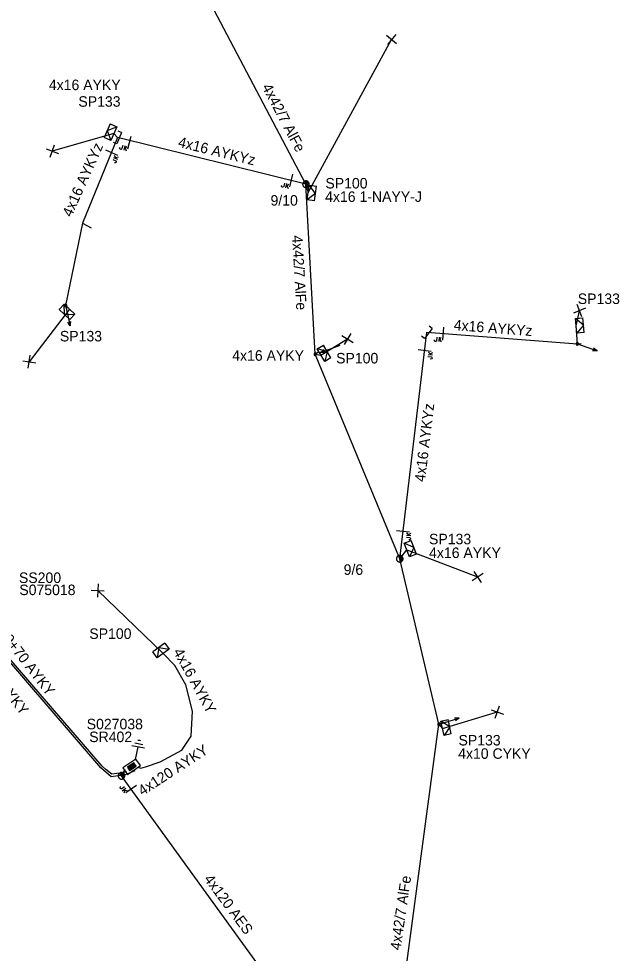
# Model space of a CAD drawing. Extents: x -788458 to -786145, y -1154772 to -1152372.
# Drawn here: x -786436.8 to -786379.6, y -1153446 to -1153357 of the extents above; entities that cross this region are included whole.
import ezdxf

# ---------------------------------------------------------------- set-up
doc = ezdxf.new("R2010")
doc.units = 0
for name, color, linetype in [('Vrstva 1', 7, 'Continuous'), ('Vrstva 12', 7, 'Continuous'), ('Vrstva 13', 7, 'Continuous'), ('Vrstva 14', 7, 'Continuous'), ('Vrstva 15', 7, 'Continuous'), ('Vrstva 18', 7, 'Continuous'), ('Vrstva 2', 7, 'Continuous'), ('Vrstva 28', 7, 'Continuous'), ('Vrstva 29', 7, 'Continuous'), ('Vrstva 30', 7, 'Continuous'), ('Vrstva 31', 7, 'Continuous'), ('Vrstva 33', 7, 'Continuous'), ('Vrstva 34', 7, 'Continuous'), ('Vrstva 5', 7, 'Continuous'), ('Vrstva 50', 7, 'Continuous'), ('Vrstva 51', 7, 'Continuous'), ('Vrstva 52', 7, 'Continuous'), ('Vrstva 53', 7, 'Continuous'), ('Vrstva 54', 7, 'Continuous'), ('Vrstva 55', 7, 'Continuous'), ('Vrstva 59', 7, 'Continuous'), ('Vrstva 6', 7, 'Continuous'), ('Vrstva 8', 7, 'Continuous'), ('Vrstva 9', 7, 'Continuous')]:
    doc.layers.add(name, color=color, linetype=linetype)

# ---------------------------------------------------------------- blocks, each defined once
blk = doc.blocks.new('NN440')
at = {"layer": 'Vrstva 2'}
for points in [[(0.63, 0), (0.63, 0.06), (0.62, 0.13), (0.6, 0.19), (0.58, 0.25), (0.55, 0.31), (0.51, 0.37), (0.47, 0.42), (0.42, 0.46), (0.37, 0.51), (0.32, 0.54), (0.26, 0.57), (0.2, 0.59), (0.13, 0.61), (0.07, 0.62), (0, 0.63), (-0.06, 0.62), (-0.13, 0.61), (-0.19, 0.59), (-0.26, 0.57), (-0.31, 0.54), (-0.37, 0.51), (-0.42, 0.46), (-0.47, 0.42), (-0.51, 0.37), (-0.54, 0.31), (-0.57, 0.25), (-0.6, 0.19), (-0.62, 0.13), (-0.63, 0.06), (-0.63, 0), (-0.63, -0.07), (-0.62, -0.14), (-0.6, -0.2), (-0.57, -0.26), (-0.54, -0.32), (-0.51, -0.37), (-0.47, -0.43), (-0.42, -0.47), (-0.37, -0.51), (-0.31, -0.55), (-0.26, -0.58), (-0.19, -0.6), (-0.13, -0.62), (-0.06, -0.63), (0, -0.63), (0.07, -0.63), (0.13, -0.62), (0.2, -0.6), (0.26, -0.58), (0.32, -0.55), (0.37, -0.51), (0.42, -0.47), (0.47, -0.43), (0.51, -0.37), (0.55, -0.32), (0.58, -0.26), (0.6, -0.2), (0.62, -0.14), (0.63, -0.07), (0.63, 0)], [(-0.63, 0), (0.63, 0)], [(-0.6, -0.18), (0.57, -0.18)], [(-0.51, -0.32), (0.5, -0.32)], [(-0.37, -0.47), (0.35, -0.47)]]:
    blk.add_lwpolyline(points, dxfattribs=at)
blk = doc.blocks.new('NN560')
at = {"layer": 'Vrstva 2'}
for points in [[(1.999, -0.001), (1.59, 0.141)], [(0, -0.001), (1.999, -0.001)], [(1.999, -0.001), (1.59, -0.134)]]:
    blk.add_lwpolyline(points, dxfattribs=at)
blk = doc.blocks.new('NN840')
at = {"layer": 'Vrstva 15'}
for points in [[(0.003, 0.619), (0.003, -0.631)], [(-0.745, -0.71), (-0.745, -0.66)], [(-0.73, -0.764), (-0.745, -0.71)], [(-0.657, -0.798), (-0.73, -0.764)], [(-0.627, -0.798), (-0.657, -0.798)], [(-0.558, -0.764), (-0.627, -0.798)], [(-0.538, -0.71), (-0.558, -0.764)], [(-0.538, -0.385), (-0.538, -0.71)], [(-0.332, -0.385), (-0.332, -0.798)], [(-0.332, -0.641), (-0.125, -0.385)], [(-0.263, -0.557), (-0.091, -0.798)]]:
    blk.add_lwpolyline(points, dxfattribs=at)
blk = doc.blocks.new('NN565')
at = {"layer": 'Vrstva 2'}
for points in [[(0.015, 0.528), (0.015, 2.528)], [(0.157, 0.937), (0.015, 0.528), (-0.119, 0.937)]]:
    blk.add_lwpolyline(points, dxfattribs=at)
blk = doc.blocks.new('NN800')
at = {"layer": 'Vrstva 1'}
for points in [[(-0.442, 0.442), (0.442, -0.442)], [(-0.442, -0.442), (0.442, 0.442)]]:
    blk.add_lwpolyline(points, dxfattribs=at)
blk = doc.blocks.new('NN620')
at = {"layer": 'Vrstva 8'}
for points in [[(0.752, 0.004), (-0.748, 0.004)], [(-0.748, 0.004), (-0.748, -0.746)], [(0.752, -0.746), (0.752, 0.004)], [(-0.748, -0.746), (0.752, -0.746)], [(0.368, -0.18), (-0.376, -0.18)], [(-0.376, -0.18), (-0.376, -0.558)], [(-0.376, -0.558), (0.368, -0.558)], [(0.321, -0.227), (-0.329, -0.227)], [(-0.329, -0.227), (-0.329, -0.51)], [(-0.329, -0.51), (0.321, -0.51)], [(0.274, -0.274), (-0.281, -0.274)], [(-0.281, -0.274), (-0.281, -0.463)], [(-0.281, -0.463), (0.274, -0.463)], [(0.227, -0.321), (-0.234, -0.321)], [(-0.234, -0.321), (-0.234, -0.416)], [(-0.234, -0.416), (0.227, -0.416)], [(-0.193, -0.369), (0.185, -0.369)], [(0.227, -0.416), (0.227, -0.321)], [(0.274, -0.463), (0.274, -0.274)], [(0.321, -0.51), (0.321, -0.227)], [(0.368, -0.558), (0.368, -0.18)]]:
    blk.add_lwpolyline(points, dxfattribs=at)
blk = doc.blocks.new('NN630')
at = {"layer": 'Vrstva 9'}
for points in [[(-0.003, -0.7), (-0.703, 0)], [(-0.703, -0.7), (-0.703, 0), (0.697, 0), (0.697, -0.7)], [(-0.703, -0.7), (0.697, -0.7)], [(-0.003, -0.7), (0.697, 0)]]:
    blk.add_lwpolyline(points, dxfattribs=at)
blk = doc.blocks.new('NN810')
at = {"layer": 'Vrstva 14'}
for points in [[(0.004, -0.64), (0.004, -1.89)], [(0.629, -1.89), (-0.621, -1.89)], [(0.388, -2.2), (-0.399, -2.2)], [(0.004, -2.515), (-0.124, -2.515)], [(0.137, -2.515), (0.004, -2.515)]]:
    blk.add_lwpolyline(points, dxfattribs=at)
blk = doc.blocks.new('NN500')
at = {"layer": 'Vrstva 2'}
for points in [[(0, -0.24), (0.02, -0.23), (0.05, -0.23), (0.07, -0.22), (0.09, -0.22), (0.12, -0.2), (0.14, -0.19), (0.16, -0.18), (0.17, -0.16), (0.19, -0.14), (0.2, -0.12), (0.21, -0.1), (0.22, -0.07), (0.23, -0.05), (0.23, -0.02), (0.23, 0), (0.23, 0.02), (0.23, 0.05), (0.22, 0.07), (0.21, 0.1), (0.2, 0.12), (0.19, 0.14), (0.17, 0.16), (0.16, 0.17), (0.14, 0.19), (0.12, 0.2), (0.09, 0.21), (0.07, 0.22), (0.05, 0.23), (0.02, 0.23), (0, 0.23), (-0.03, 0.23), (-0.05, 0.23), (-0.07, 0.22), (-0.1, 0.21), (-0.12, 0.2), (-0.14, 0.19), (-0.16, 0.17), (-0.18, 0.16), (-0.19, 0.14), (-0.2, 0.12), (-0.22, 0.1), (-0.22, 0.07), (-0.23, 0.05), (-0.23, 0.02), (-0.24, 0), (-0.23, -0.02), (-0.23, -0.05), (-0.22, -0.07), (-0.22, -0.1), (-0.2, -0.12), (-0.19, -0.14), (-0.18, -0.16), (-0.16, -0.18), (-0.14, -0.19), (-0.12, -0.2), (-0.1, -0.22), (-0.07, -0.22), (-0.05, -0.23), (-0.03, -0.23), (0, -0.24)], [(0, -0.24), (0.02, -0.23), (0.05, -0.23), (0.07, -0.22), (0.09, -0.22), (0.12, -0.2), (0.14, -0.19), (0.16, -0.18), (0.17, -0.16), (0.19, -0.14), (0.2, -0.12), (0.21, -0.1), (0.22, -0.07), (0.23, -0.05), (0.23, -0.02), (0.23, 0), (0.23, 0.02), (0.23, 0.05), (0.22, 0.07), (0.21, 0.1), (0.2, 0.12), (0.19, 0.14), (0.17, 0.16), (0.16, 0.17), (0.14, 0.19), (0.12, 0.2), (0.09, 0.21), (0.07, 0.22), (0.05, 0.23), (0.02, 0.23), (0, 0.23), (-0.03, 0.23), (-0.05, 0.23), (-0.07, 0.22), (-0.1, 0.21), (-0.12, 0.2), (-0.14, 0.19), (-0.16, 0.17), (-0.18, 0.16), (-0.19, 0.14), (-0.2, 0.12), (-0.22, 0.1), (-0.22, 0.07), (-0.23, 0.05), (-0.23, 0.02), (-0.24, 0), (-0.23, -0.02), (-0.23, -0.05), (-0.22, -0.07), (-0.22, -0.1), (-0.2, -0.12), (-0.19, -0.14), (-0.18, -0.16), (-0.16, -0.18), (-0.14, -0.19), (-0.12, -0.2), (-0.1, -0.22), (-0.07, -0.22), (-0.05, -0.23), (-0.03, -0.23), (0, -0.24)], [(0, -0.21), (0.02, -0.2), (0.04, -0.2), (0.06, -0.2), (0.08, -0.19), (0.1, -0.18), (0.12, -0.17), (0.14, -0.15), (0.15, -0.14), (0.16, -0.12), (0.18, -0.1), (0.19, -0.08), (0.19, -0.06), (0.2, -0.04), (0.2, -0.02), (0.2, 0), (0.2, 0.02), (0.2, 0.04), (0.19, 0.06), (0.19, 0.08), (0.18, 0.1), (0.16, 0.12), (0.15, 0.14), (0.14, 0.15), (0.12, 0.17), (0.1, 0.18), (0.08, 0.19), (0.06, 0.19), (0.04, 0.2), (0.02, 0.2), (0, 0.2), (-0.02, 0.2), (-0.04, 0.2), (-0.06, 0.19), (-0.08, 0.19), (-0.1, 0.18), (-0.12, 0.17), (-0.14, 0.15), (-0.15, 0.14), (-0.17, 0.12), (-0.18, 0.1), (-0.19, 0.08), (-0.2, 0.06), (-0.2, 0.04), (-0.21, 0.02), (-0.21, 0), (-0.21, -0.02), (-0.2, -0.04), (-0.2, -0.06), (-0.19, -0.08), (-0.18, -0.1), (-0.17, -0.12), (-0.15, -0.14), (-0.14, -0.15), (-0.12, -0.17), (-0.1, -0.18), (-0.08, -0.19), (-0.06, -0.2), (-0.04, -0.2), (-0.02, -0.2), (0, -0.21)], [(0, -0.18), (0.02, -0.18), (0.04, -0.17), (0.05, -0.17), (0.07, -0.16), (0.09, -0.15), (0.1, -0.14), (0.12, -0.13), (0.13, -0.12), (0.14, -0.1), (0.15, -0.09), (0.16, -0.07), (0.17, -0.05), (0.17, -0.04), (0.17, -0.02), (0.17, 0), (0.17, 0.02), (0.17, 0.04), (0.17, 0.05), (0.16, 0.07), (0.15, 0.09), (0.14, 0.1), (0.13, 0.12), (0.12, 0.13), (0.1, 0.14), (0.09, 0.15), (0.07, 0.16), (0.05, 0.17), (0.04, 0.17), (0.02, 0.17), (0, 0.18), (-0.02, 0.17), (-0.04, 0.17), (-0.06, 0.17), (-0.07, 0.16), (-0.09, 0.15), (-0.1, 0.14), (-0.12, 0.13), (-0.13, 0.12), (-0.14, 0.1), (-0.15, 0.09), (-0.16, 0.07), (-0.17, 0.05), (-0.17, 0.04), (-0.18, 0.02), (-0.18, 0), (-0.18, -0.02), (-0.17, -0.04), (-0.17, -0.05), (-0.16, -0.07), (-0.15, -0.09), (-0.14, -0.1), (-0.13, -0.12), (-0.12, -0.13), (-0.1, -0.14), (-0.09, -0.15), (-0.07, -0.16), (-0.06, -0.17), (-0.04, -0.17), (-0.02, -0.18), (0, -0.18)], [(0, -0.15), (0.01, -0.15), (0.03, -0.14), (0.04, -0.14), (0.06, -0.13), (0.07, -0.13), (0.08, -0.12), (0.1, -0.11), (0.11, -0.1), (0.12, -0.09), (0.13, -0.07), (0.13, -0.06), (0.14, -0.05), (0.14, -0.03), (0.14, -0.02), (0.14, 0), (0.14, 0.01), (0.14, 0.03), (0.14, 0.04), (0.13, 0.06), (0.13, 0.07), (0.12, 0.09), (0.11, 0.1), (0.1, 0.11), (0.08, 0.12), (0.07, 0.13), (0.06, 0.13), (0.04, 0.14), (0.03, 0.14), (0.01, 0.14), (0, 0.15), (-0.02, 0.14), (-0.03, 0.14), (-0.05, 0.14), (-0.06, 0.13), (-0.07, 0.13), (-0.09, 0.12), (-0.1, 0.11), (-0.11, 0.1), (-0.12, 0.09), (-0.13, 0.07), (-0.13, 0.06), (-0.14, 0.04), (-0.14, 0.03), (-0.15, 0.01), (-0.15, 0), (-0.15, -0.02), (-0.14, -0.03), (-0.14, -0.05), (-0.13, -0.06), (-0.13, -0.07), (-0.12, -0.09), (-0.11, -0.1), (-0.1, -0.11), (-0.09, -0.12), (-0.07, -0.13), (-0.06, -0.13), (-0.05, -0.14), (-0.03, -0.14), (-0.02, -0.15), (0, -0.15)], [(0, -0.12), (0.01, -0.12), (0.02, -0.11), (0.03, -0.11), (0.05, -0.11), (0.06, -0.1), (0.07, -0.09), (0.08, -0.09), (0.09, -0.08), (0.09, -0.07), (0.1, -0.06), (0.11, -0.05), (0.11, -0.04), (0.11, -0.02), (0.11, -0.01), (0.12, 0), (0.11, 0.01), (0.11, 0.02), (0.11, 0.04), (0.11, 0.05), (0.1, 0.06), (0.09, 0.07), (0.09, 0.08), (0.08, 0.09), (0.07, 0.09), (0.06, 0.1), (0.05, 0.11), (0.03, 0.11), (0.02, 0.11), (0.01, 0.12), (0, 0.12), (-0.01, 0.12), (-0.03, 0.11), (-0.04, 0.11), (-0.05, 0.11), (-0.06, 0.1), (-0.07, 0.09), (-0.08, 0.09), (-0.09, 0.08), (-0.1, 0.07), (-0.1, 0.06), (-0.11, 0.05), (-0.11, 0.04), (-0.12, 0.02), (-0.12, 0.01), (-0.12, 0), (-0.12, -0.01), (-0.12, -0.02), (-0.11, -0.04), (-0.11, -0.05), (-0.1, -0.06), (-0.1, -0.07), (-0.09, -0.08), (-0.08, -0.09), (-0.07, -0.09), (-0.06, -0.1), (-0.05, -0.11), (-0.04, -0.11), (-0.03, -0.11), (-0.01, -0.12), (0, -0.12)], [(0, -0.09), (0.01, -0.09), (0.02, -0.09), (0.03, -0.08), (0.03, -0.08), (0.04, -0.08), (0.05, -0.07), (0.06, -0.07), (0.06, -0.06), (0.07, -0.05), (0.07, -0.04), (0.08, -0.04), (0.08, -0.03), (0.08, -0.02), (0.09, -0.01), (0.09, 0), (0.09, 0.01), (0.08, 0.02), (0.08, 0.03), (0.08, 0.03), (0.07, 0.04), (0.07, 0.05), (0.06, 0.06), (0.06, 0.06), (0.05, 0.07), (0.04, 0.07), (0.03, 0.08), (0.03, 0.08), (0.02, 0.08), (0.01, 0.09), (0, 0.09), (-0.01, 0.09), (-0.02, 0.08), (-0.03, 0.08), (-0.04, 0.08), (-0.04, 0.07), (-0.05, 0.07), (-0.06, 0.06), (-0.07, 0.06), (-0.07, 0.05), (-0.08, 0.04), (-0.08, 0.03), (-0.08, 0.03), (-0.09, 0.02), (-0.09, 0.01), (-0.09, 0), (-0.09, -0.01), (-0.09, -0.02), (-0.08, -0.03), (-0.08, -0.04), (-0.08, -0.04), (-0.07, -0.05), (-0.07, -0.06), (-0.06, -0.07), (-0.05, -0.07), (-0.04, -0.08), (-0.04, -0.08), (-0.03, -0.08), (-0.02, -0.09), (-0.01, -0.09), (0, -0.09)], [(0, -0.06), (0, -0.06), (0.01, -0.06), (0.02, -0.05), (0.02, -0.05), (0.03, -0.05), (0.03, -0.05), (0.04, -0.04), (0.04, -0.04), (0.05, -0.03), (0.05, -0.03), (0.05, -0.02), (0.05, -0.02), (0.05, -0.01), (0.06, -0.01), (0.06, 0), (0.06, 0.01), (0.05, 0.01), (0.05, 0.02), (0.05, 0.02), (0.05, 0.03), (0.05, 0.03), (0.04, 0.04), (0.04, 0.04), (0.03, 0.05), (0.03, 0.05), (0.02, 0.05), (0.02, 0.05), (0.01, 0.06), (0, 0.06), (0, 0.06), (-0.01, 0.06), (-0.01, 0.06), (-0.02, 0.05), (-0.02, 0.05), (-0.03, 0.05), (-0.03, 0.05), (-0.04, 0.04), (-0.04, 0.04), (-0.05, 0.03), (-0.05, 0.03), (-0.05, 0.02), (-0.06, 0.02), (-0.06, 0.01), (-0.06, 0.01), (-0.06, 0), (-0.06, -0.01), (-0.06, -0.01), (-0.06, -0.02), (-0.05, -0.02), (-0.05, -0.03), (-0.05, -0.03), (-0.04, -0.04), (-0.04, -0.04), (-0.03, -0.05), (-0.03, -0.05), (-0.02, -0.05), (-0.02, -0.05), (-0.01, -0.06), (-0.01, -0.06), (0, -0.06)], [(0, -0.03), (0, -0.03), (0, -0.03), (0.01, -0.03), (0.01, -0.03), (0.01, -0.02), (0.02, -0.02), (0.02, -0.02), (0.02, -0.02), (0.02, -0.02), (0.02, -0.01), (0.02, -0.01), (0.03, -0.01), (0.03, -0.01), (0.03, 0), (0.03, 0), (0.03, 0), (0.03, 0.01), (0.03, 0.01), (0.02, 0.01), (0.02, 0.01), (0.02, 0.02), (0.02, 0.02), (0.02, 0.02), (0.02, 0.02), (0.01, 0.02), (0.01, 0.02), (0.01, 0.03), (0, 0.03), (0, 0.03), (0, 0.03), (0, 0.03), (-0.01, 0.03), (-0.01, 0.03), (-0.01, 0.02), (-0.02, 0.02), (-0.02, 0.02), (-0.02, 0.02), (-0.02, 0.02), (-0.02, 0.02), (-0.03, 0.01), (-0.03, 0.01), (-0.03, 0.01), (-0.03, 0.01), (-0.03, 0), (-0.03, 0), (-0.03, 0), (-0.03, -0.01), (-0.03, -0.01), (-0.03, -0.01), (-0.03, -0.01), (-0.02, -0.02), (-0.02, -0.02), (-0.02, -0.02), (-0.02, -0.02), (-0.02, -0.02), (-0.01, -0.03), (-0.01, -0.03), (-0.01, -0.03), (0, -0.03), (0, -0.03)], [(0.23, 0), (0.7, 0)]]:
    blk.add_lwpolyline(points, dxfattribs=at)
blk = doc.blocks.new('NN510')
at = {"layer": 'Vrstva 2'}
blk.add_lwpolyline([(0.001, 0.002), (0.001, 0.939)], dxfattribs=at)
blk = doc.blocks.new('NN515')
at = {"layer": 'Vrstva 2'}
for points in [[(-0.59, 0.176), (0.591, 0.176)], [(-0.59, 0.176), (-0.59, -0.179)], [(0.591, 0.176), (0.591, -0.179)]]:
    blk.add_lwpolyline(points, dxfattribs=at)

msp = doc.modelspace()

# ---------------------------------------------------------------- linework, layer by layer
at = {"layer": 'Vrstva 1'}
for points in [[(-786409.44, -1153372.75), (-786422.249, -1153348.421)], [(-786400.51, -1153408.42), (-786408.55, -1153388.94), (-786409.44, -1153372.75)], [(-786401.25, -1153457.626), (-786396.77, -1153424.18), (-786400.51, -1153408.42)]]:
    msp.add_lwpolyline(points, dxfattribs=at)
at = {"layer": 'Vrstva 5'}
for points in [[(-786426.497, -1153428.752), (-786427.931, -1153428.949), (-786428.49, -1153428.489), (-786428.849, -1153428.179), (-786438.521, -1153416.958), (-786440.886, -1153413.606), (-786441.702, -1153412.233), (-786443.421, -1153408.614), (-786443.215, -1153408.651), (-786441.481, -1153409.008), (-786439.123, -1153409.542), (-786438.422, -1153409.075)], [(-786425.745, -1153428.616), (-786426.648, -1153429.009), (-786428.002, -1153429.175), (-786428.991, -1153428.321), (-786438.679, -1153417.082)], [(-786426.679, -1153428.481), (-786427.01, -1153429.09)]]:
    msp.add_lwpolyline(points, dxfattribs=at)
at = {"layer": 'Vrstva 50'}
msp.add_lwpolyline([(-786402.361, -1153457.407), (-786413.72, -1153447.47), (-786427.01, -1153429.09)], dxfattribs=at)
at = {"layer": 'Vrstva 52'}
for points in [[(-786427.39, -1153368.3), (-786427.74, -1153367.93)], [(-786409.44, -1153372.75), (-786427.39, -1153368.3)], [(-786409.44, -1153372.75), (-786409.23, -1153373.53)], [(-786400.51, -1153408.42), (-786397.93, -1153386.85)], [(-786408.55, -1153388.94), (-786408.02, -1153389.03)], [(-786400.51, -1153408.42), (-786399.83, -1153407.58)], [(-786425.468, -1153428.259), (-786425.164, -1153428.363), (-786424.71, -1153428.25), (-786423.32, -1153427.77), (-786421.26, -1153426.65), (-786420.37, -1153425.32), (-786420.24, -1153422.94), (-786420.89, -1153420.44), (-786421.92, -1153418.57), (-786423.05, -1153417.44)], [(-786396.77, -1153424.18), (-786396.43, -1153424.57)]]:
    msp.add_lwpolyline(points, dxfattribs=at)
at = {"layer": 'Vrstva 54'}
for points in [[(-786427.39, -1153368.3), (-786430.73, -1153376.44), (-786432.33, -1153384.29), (-786431.97, -1153384.64)], [(-786397.93, -1153386.85), (-786383.59, -1153387.95), (-786383.699, -1153386.232)]]:
    msp.add_lwpolyline(points, dxfattribs=at)
at = {"layer": 'Vrstva 59'}
for points in [[(-786409.23, -1153373.53), (-786401.284, -1153358.952)], [(-786427.74, -1153367.93), (-786433.6, -1153369.59)], [(-786431.97, -1153384.64), (-786435.8, -1153389.66)], [(-786383.699, -1153386.232), (-786383.386, -1153384.792)], [(-786408.02, -1153389.03), (-786405.488, -1153387.486)], [(-786399.83, -1153407.58), (-786393.09, -1153410.15)], [(-786423.05, -1153417.44), (-786429.28, -1153411.44)], [(-786396.43, -1153424.57), (-786391.21, -1153423.01)]]:
    msp.add_lwpolyline(points, dxfattribs=at)

# ---------------------------------------------------------------- block references
at = {"layer": 'Vrstva 13'}
for name, p, rotation in [('NN515', (-786427.39, -1153368.3), -112.30929458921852), ('NN510', (-786430.73, -1153376.44), -118.5000527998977), ('NN560', (-786432.33, -1153384.29), -77.35100834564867), ('NN515', (-786397.93, -1153386.85), -127.14855002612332), ('NN565', (-786408.55, -1153388.94), -69.58919161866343), ('NN560', (-786383.59, -1153387.95), -19.790833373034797), ('NN560', (-786396.77, -1153424.18), 16.429380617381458)]:
    msp.add_blockref(name, p, dxfattribs=dict(at, rotation=rotation))
for name, p, xscale, yscale, rotation in [('NN440', (-786409.44, -1153372.75), 0.49999999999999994, 0.5000000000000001, 93.33133329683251), ('NN500', (-786432.33, -1153384.29), 0.5, 0.5, -49.145000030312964), ('NN500', (-786383.59, -1153387.95), 0.5, 0.5, 2.952000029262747), ('NN500', (-786408.55, -1153388.94), 0.5, 0.5, 38.531000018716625), ('NN440', (-786400.51, -1153408.42), 0.5, 0.49999999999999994, 108.32045828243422), ('NN500', (-786396.77, -1153424.18), 0.5, 0.5, 16.21600013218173), ('NN440', (-786427.01, -1153429.09), 0.49999999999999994, 0.5000000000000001, 128.86800012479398)]:
    msp.add_blockref(name, p, dxfattribs=dict(at, xscale=xscale, yscale=yscale, rotation=rotation))
at = {"layer": 'Vrstva 15', "rotation": 169.2034355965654}
msp.add_blockref('NN810', (-786425.779, -1153428.181), dxfattribs=at)
at = {"layer": 'Vrstva 18'}
for p, rotation in [((-786426.285, -1153368.798), -13.767697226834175), ((-786427.978, -1153369.733), 66.00056107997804), ((-786410.864, -1153372.397), -13.923530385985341), ((-786396.401, -1153386.967), -4.386483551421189), ((-786398.136, -1153388.573), 83.17922353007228), ((-786400.195, -1153405.79), 83.1792234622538), ((-786426.095, -1153430.358), -55.276913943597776)]:
    msp.add_blockref('NN840', p, dxfattribs=dict(at, rotation=rotation))
at = {"layer": 'Vrstva 28', "rotation": -145.35089093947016}
msp.add_blockref('NN620', (-786425.83, -1153428.53), dxfattribs=at)
at = {"layer": 'Vrstva 31'}
for p, rotation in [((-786427.74, -1153367.93), -113.79870919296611), ((-786409.23, -1153373.53), 82.27136294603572), ((-786431.97, -1153384.64), -43.051914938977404), ((-786383.699, -1153386.232), 94.24474165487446), ((-786408.02, -1153389.03), 121.17134902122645), ((-786399.83, -1153407.58), 111.13557820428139), ((-786423.05, -1153417.44), -144.69863055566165), ((-786396.43, -1153424.57), 102.30801581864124)]:
    msp.add_blockref('NN630', p, dxfattribs=dict(at, rotation=rotation))
at = {"layer": 'Vrstva 34'}
for p, rotation in [((-786401.284, -1153358.952), -84.97763053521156), ((-786433.6, -1153369.59), 24.70228054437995), ((-786383.386, -1153384.792), 156.24507505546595), ((-786405.488, -1153387.486), -76.3051027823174), ((-786435.8, -1153389.66), 36.78174443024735), ((-786393.09, -1153410.15), -10.722944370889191), ((-786429.28, -1153411.44), -47.86996117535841), ((-786391.21, -1153423.01), 25.685638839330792)]:
    msp.add_blockref('NN800', p, dxfattribs=dict(at, rotation=rotation))

# ---------------------------------------------------------------- texts
at = {"layer": 'Vrstva 12'}
for s, p in [('9/10', (-786412.817, -1153374.784)), ('9/6', (-786405.85, -1153409.95))]:
    msp.add_text(s, height=1, dxfattribs=at).set_placement(p)
at = {"layer": 'Vrstva 2'}
for rotation, p in [(297.766, (-786413.657, -1153363.482)), (273.331, (-786410.769, -1153377.639)), (81.737, (-786400.437, -1153445.737))]:
    msp.add_text('4x42/7 AlFe', height=1, rotation=rotation, dxfattribs=at).set_placement(p)
at = {"layer": 'Vrstva 29'}
for s, p in [('S075018', (-786436.745, -1153411.878)), ('S027038', (-786430.325, -1153424.661))]:
    msp.add_text(s, height=1, dxfattribs=at).set_placement(p)
at = {"layer": 'Vrstva 30'}
for s, p in [('SS200', (-786436.779, -1153410.724)), ('SR402', (-786430.086, -1153425.878))]:
    msp.add_text(s, height=1, dxfattribs=at).set_placement(p)
at = {"layer": 'Vrstva 33'}
for s, p in [('SP133', (-786431.119, -1153365.365)), ('SP100', (-786407.59, -1153373.152)), ('SP133', (-786383.548, -1153384.154)), ('SP133', (-786432.88, -1153387.717)), ('SP100', (-786406.568, -1153389.813)), ('SP133', (-786397.718, -1153407.04)), ('SP100', (-786430.076, -1153416.05)), ('SP133', (-786394.91, -1153426.2))]:
    msp.add_text(s, height=1, dxfattribs=at).set_placement(p)
at = {"layer": 'Vrstva 51'}
msp.add_text('4x120 AES', height=1, rotation=306.653, dxfattribs=at).set_placement((-786419.206, -1153438.935))
at = {"layer": 'Vrstva 53'}
for rotation, p in [(346.232, (-786421.688, -1153369.177)), (83.179, (-786398.104, -1153401.135))]:
    msp.add_text('4x16 AYKYz', height=1, rotation=rotation, dxfattribs=at).set_placement(p)
at = {"layer": 'Vrstva 54'}
for s, p in [('4x16 AYKY', (-786433.929, -1153363.785)), ('4x16 1-NAYY-J', (-786407.613, -1153374.43)), ('4x16 AYKY', (-786416.464, -1153389.558)), ('4x16 AYKY', (-786397.711, -1153408.344)), ('4x10 CYKY', (-786394.942, -1153427.47))]:
    msp.add_text(s, height=1, dxfattribs=at).set_placement(p)
msp.add_text('4x16 AYKY', height=1, rotation=298.847, dxfattribs=at).set_placement((-786422.116, -1153417.271))
at = {"layer": 'Vrstva 55'}
for rotation, p in [(66, (-786431.78, -1153375.939)), (355.614, (-786395.387, -1153386.638))]:
    msp.add_text('4x16 AYKYz', height=1, rotation=rotation, dxfattribs=at).set_placement(p)
at = {"layer": 'Vrstva 6'}
for s, rotation, p in [('3x120+70 AYKY', 308.016, (-786440.124, -1153413.798)), ('3x120+70 AYKY', 308.021, (-786442.614, -1153415.638)), ('4x120 AYKY', 33.068, (-786425.017, -1153431.029))]:
    msp.add_text(s, height=1, rotation=rotation, dxfattribs=at).set_placement(p)

doc.saveas('drawing.dxf')
